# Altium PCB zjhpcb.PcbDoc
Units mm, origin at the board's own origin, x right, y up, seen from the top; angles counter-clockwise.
Board outline 152.4 x 101.6 mm, 4 copper layers (Top, GND, POWER, Bottom), stack 0.776 mm thick; 108 components, 81 nets, 341 pads, 2 vias.
Unrouted connection lines stored in the file: 172.
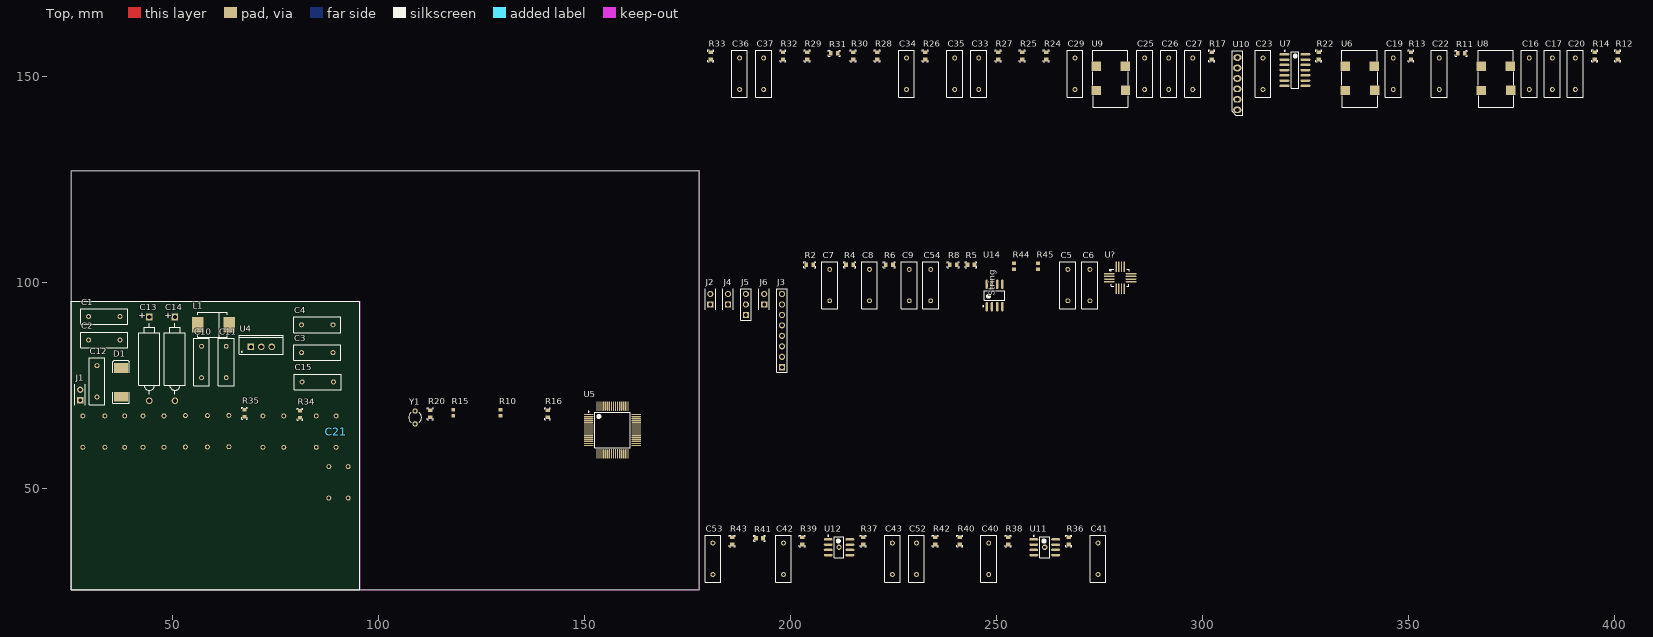
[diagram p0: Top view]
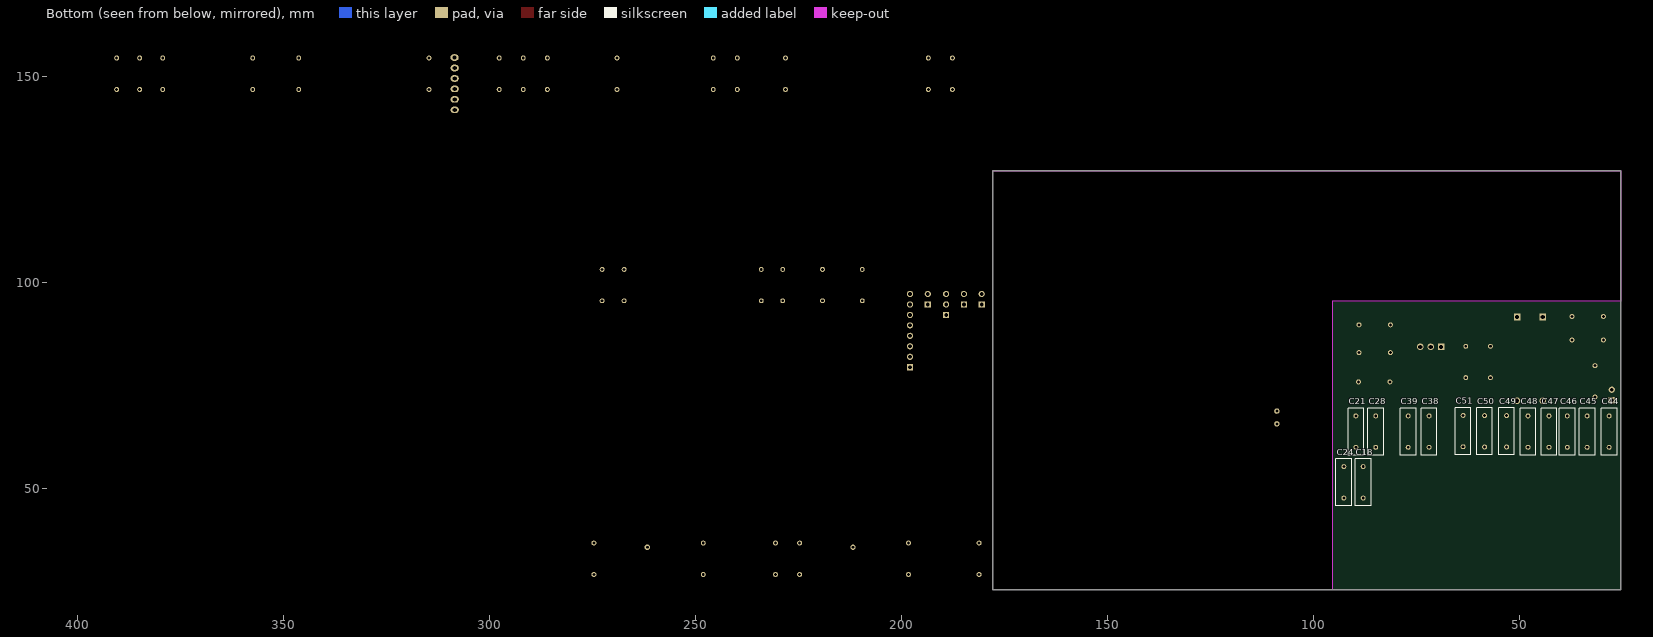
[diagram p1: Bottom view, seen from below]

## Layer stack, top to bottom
Top Solder: solder mask 0.0102, Solder Resist, Dk 3.5
Top: signal copper 0.0356
Dielectric 2: prepreg 0.254, PP-006, Dk 4.1
GND: signal copper 0.035
Dielectric 1: dielectric 0.127, FR-4, Dk 4.8
POWER: signal copper 0.035
Dielectric 3: prepreg 0.254, PP-006, Dk 4.1
Bottom: signal copper 0.0356
Bottom Solder: solder mask 0.0102, Solder Resist, Dk 3.5

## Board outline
25.4,25.4 177.8,25.4 177.8,127 25.4,127
cut-out: 25.4,127 25.4,95.377 95.377,95.377 95.377,25.4 177.8,25.4 177.8,127

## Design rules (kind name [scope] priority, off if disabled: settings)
Clearance [All] p1: gap=0.254 ignorepadtopadclearanceinfootprint=FALSE except(0: Arc-Hole Track-Hole SMDPad-Hole THPad-Hole Via-Hole Fill-Hole Poly-Hole Region-Hole Text-Hole)
PolygonConnect [All] p1: connectstyle=Relief reliefconductorwidth=0.254 reliefentries=4 polygonreliefangle="90 Angle" airgapwidth=0.254
RoomDefinition U_陀螺仪模块 [InComponentClass('U_陀螺仪模块')] p1: confinementstyle=ConfineIn formatcopy=TRUE outline 179.578,140.183 404.368,140.183 404.368,159.106 179.578,159.106
RoomDefinition U_电源模块 [InComponentClass('U_电源模块')] p2: confinementstyle=ConfineIn formatcopy=TRUE outline 25.908,69.85 104.521,69.85 104.521,94.996 25.908,94.996
RoomDefinition U_信号输入模块 [InComponentClass('U_信号输入模块')] p3: confinementstyle=ConfineIn formatcopy=TRUE outline 178.943,77.851 199.771,77.851 199.771,101.219 178.943,101.219
RoomDefinition U_传感器监测模块 [InComponentClass('U_传感器监测模块')] p4: confinementstyle=ConfineIn formatcopy=TRUE outline 202.971,92.583 284.124,92.583 284.124,107.823 202.971,107.823
RoomDefinition U_主控模块 [InComponentClass('U_主控模块')] p5: confinementstyle=ConfineIn formatcopy=TRUE outline 178.943,42.545 313.436,42.545 313.436,60.071 178.943,60.071
RoomDefinition U_CAN总线模块 [InComponentClass('U_CAN总线模块')] p6: confinementstyle=ConfineIn formatcopy=TRUE outline 178.943,26.924 276.86,26.924 276.86,41.402 178.943,41.402
RoutingVias [All] p1: holewidth=0.254 width=0.508 viastyle="Through Hole" minholewidth=0.254 minwidth=0.508 maxholewidth=0.254 maxwidth=0.508
SolderMaskExpansion [All] p1: expansion=0.102
Width [All] p1: maxlimit=0.254 minlimit=0.254 preferedwidth=0.254
Width POWER [All] p2: maxlimit=0.762 minlimit=0.508 preferedwidth=0.508
Width GND [All] p3: maxlimit=0.762 minlimit=0.508 preferedwidth=0.508
30 further rules are at their usual default settings.

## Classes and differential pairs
component class U_电源模块: C1 C2 C3 C4 C10 C11 C12 C13 C14 C15 D1 J1 L1 U1 U4
component class U_陀螺仪模块: C16 C17 C19 C20 C22 C23 C25 C26 C27 C29 C33 C34 C35 C36 C37 R11 R12 R13 R14 R17 R22 R24 R25 R26 R27 R28 R29 R30 R31 R32 R33 U6 U7 U8 U9 U10
component class U_信号输入模块: J2 J3 J4 J5 J6
component class U_传感器监测模块: C5 C6 C7 C8 C9 C54 R2 R4 R5 R6 R8 R44 R45 U2 U14 U?
component class U_主控模块: C18 C21 C24 C28 C38 C39 C44 C45 C46 C47 C48 C49 C50 C51 R10 R15 R16 R20 R34 R35 U5 Y1
component class U_CAN总线模块: C40 C41 C42 C43 C52 C53 R36 R37 R38 R39 R40 R41 R42 R43 U11 U12

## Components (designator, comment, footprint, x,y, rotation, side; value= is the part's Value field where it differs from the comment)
C1 "Cap" RAD-0.3 33.401,91.694 r180 top value=0.1uF
C2 "Cap" RAD-0.3 33.401,85.979 r180 top value=10uF
C3 "Cap" RAD-0.3 85.09,82.931 r180 top value=0.1uF
C4 "Cap" RAD-0.3 85.09,89.662 r180 top value=10uF
C5 "Cap" RAD-0.3 267.233,99.314 r90 top value=0.1uF
C6 "Cap" RAD-0.3 272.567,99.314 r90 top value=0.1uF
C7 "Cap" RAD-0.3 209.448,99.314 r90 top value=0.1uF
C8 "Cap" RAD-0.3 219.1,99.314 r90 top value=0.1uF
C9 "Cap" RAD-0.3 228.752,99.314 r90 top value=0.1uF
C10 "Cap" RAD-0.3 57.023,80.645 r90 top value=0.1uF
C11 "Cap" RAD-0.3 62.992,80.645 r90 top value=0.1uF
C12 "Cap" RAD-0.3 31.623,75.946 r90 top value=1uF
C13 "Cap Pol2" POLAR0.8 44.323,81.407 r90 top value=470uF
C14 "Cap Pol2" POLAR0.8 50.546,81.407 r90 top value=470uF
C15 "Cap" RAD-0.3 85.217,75.819 r180 top value=10uF
C16 "Cap" RAD-0.3 379.222,150.597 r90 top value=22pF
C17 "Cap" RAD-0.3 384.81,150.597 r90 top value=22pF
C18 "Cap" RAD-0.3 87.884,51.435 r90 bottom value=20uF
C19 "Cap" RAD-0.3 346.202,150.597 r90 top value=22uF
C20 "Cap" RAD-0.3 390.398,150.597 r90 top value=22nF
C21 "Cap" RAD-0.3 89.662,63.754 r90 top value=20uF
C22 "Cap" RAD-0.3 357.378,150.597 r90 top value=0.1uF
C23 "Cap" RAD-0.3 314.579,150.597 r90 top value=0.1uF
C24 "Cap" RAD-0.3 92.583,51.435 r90 bottom value=0.1uF
C25 "Cap" RAD-0.3 285.877,150.597 r90 top value=0.1uF
C26 "Cap" RAD-0.3 291.719,150.597 r90 top value=0.01uF
C27 "Cap" RAD-0.3 297.561,150.597 r90 top value=1uF
C28 "Cap" RAD-0.3 84.836,63.754 r90 bottom value=1uF
C29 "Cap" RAD-0.3 268.986,150.597 r90 top value=0.1uF
C33 "Cap" RAD-0.3 245.618,150.597 r90 top value=22uF
C34 "Cap" RAD-0.3 228.092,150.597 r90 top value=0.1uF
C35 "Cap" RAD-0.3 239.776,150.597 r90 top value=22nF
C36 "Cap" RAD-0.3 187.579,150.597 r90 top value=22uF
C37 "Cap" RAD-0.3 193.421,150.597 r90 top value=22nF
C38 "Cap" RAD-0.3 71.882,63.754 r90 bottom value=1uF
C39 "Cap" RAD-0.3 76.962,63.754 r90 bottom value=0.22uF
C40 "Cap" RAD-0.3 248.031,32.893 r90 top value=0.1uF
C41 "Cap" RAD-0.3 274.574,32.893 r90 top value=0.1uF
C42 "Cap" RAD-0.3 198.247,32.893 r90 top value=0.1uF
C43 "Cap" RAD-0.3 224.663,32.893 r90 top value=20pF
C44 "Cap" RAD-0.3 28.194,63.754 r90 bottom value=1uF
C45 "Cap" RAD-0.3 33.528,63.754 r90 bottom value=1uF
C46 "Cap" RAD-0.3 38.354,63.754 r90 bottom value=1uF
C47 "Cap" RAD-0.3 42.799,63.754 r90 bottom value=1uF
C48 "Cap" RAD-0.3 47.879,63.754 r90 bottom value=1uF
C49 "Cap" RAD-0.3 53.086,63.816 r90 bottom value=1uF
C50 "Cap" RAD-0.3 58.42,63.816 r90 bottom value=1uF
C51 "Cap" RAD-0.3 63.627,63.885 r90 bottom value=1uF
C52 "Cap" RAD-0.3 230.505,32.893 r90 top value=0.1uF
C53 "Cap" RAD-0.3 181.102,32.893 r90 top value=20uF
C54 "Cap" RAD-0.3 233.959,99.314 r90 top value=0.1uF
D1 "Diode" SMC 37.465,75.692 r90 top
J1 "POWER" HDR1X2 27.559,71.374 r90 top
J2 "POWER" HDR1X2 180.467,94.615 r90 top
J3 "Header 8" HDR1X8 197.866,79.375 r90 top
J4 "POWER" HDR1X2 184.785,94.615 r90 top
J5 "Header 3" HDR1X3 189.103,92.075 r90 top
J6 "POWER" HDR1X2 193.548,94.615 r90 top
L1 "47uH" DIODE_SMC 59.944,89.662 r180 top
R2 "680R" R0603 204.622,104.267 r0 top
R4 "680R" R0603 214.274,104.267 r0 top
R5 "680R" R0603 243.738,104.267 r0 top
R6 "680R" R0603 223.926,104.267 r0 top
R8 "680R" R0603 239.42,104.267 r0 top
R10 "470R" 1608[0603] 129.54,68.326 r90 top
R11 "10K" R0603 362.712,155.55 r0 top
R12 "10k" R0603 400.685,154.915 r90 top
R13 "47K" R0603 350.52,154.915 r90 top
R14 "47k" R0603 395.097,154.915 r90 top
R15 "1M" 1608[0603] 118.11,68.326 r90 top
R16 "470R" R0603 140.97,68.072 r90 top
R17 "10k" R0603 302.133,154.915 r90 top
R20 "470R" R0603 112.522,68.072 r90 top
R22 "680" R0603 328.168,154.915 r90 top
R24 "10k" R0603 262.001,154.915 r90 top
R25 "100" R0603 256.159,154.915 r90 top
R26 "100k" R0603 232.664,154.915 r90 top
R27 "2.2K" R0603 250.317,154.915 r90 top
R28 "47k" R0603 220.98,154.915 r90 top
R29 "10k" R0603 203.962,154.915 r90 top
R30 "6.8k" R0603 215.138,154.915 r90 top
R31 "100k" R0603 210.566,155.55 r0 top
R32 "220K" R0603 198.12,154.915 r90 top
R33 "100k" R0603 180.594,154.915 r90 top
R34 "220" R0603 80.899,67.945 r90 top
R35 "220" R0603 67.437,68.224 r90 top
R36 "100" R0603 267.462,37.211 r90 top
R37 "100" R0603 217.551,37.211 r90 top
R38 "100" R0603 252.73,37.211 r90 top
R39 "100" R0603 202.819,37.211 r90 top
R40 "120" R0603 241.046,37.211 r90 top
R41 "120" R0603 192.405,37.846 r0 top
R42 "100" R0603 235.077,37.211 r90 top
R43 "100" R0603 185.801,37.211 r90 top
R44 "10K" 1608[0603] 254.152,103.886 r90 top
R45 "10K" 1608[0603] 259.994,103.886 r90 top
U4 "LM7805" TO-220AB 71.501,84.328 r0 top
U5 "Infineon XE162" "Infineon XE162" 156.718,64.135 r0 top
U6 "ENC03" ENC03 338.074,149.454 r90 top
U7 "TLV2374" "TLV 2374" 322.326,151.486 r0 top
U8 "ENC03" ENC03 371.094,149.454 r90 top
U9 "ENC03" ENC03 277.622,149.454 r90 top
U10 "MPX4115" MPX4115 308.356,141.834 r90 top
U11 "CAN收发器" CAN 261.62,35.687 r0 top
U12 "CAN收发器" CAN 211.709,35.687 r0 top
U14 "LM75A(Tempeture)" LM75A 249.453,96.774 r90 top
U? "LIS344ALH" LIS344ALH(Acc) 279.933,101.092 r0 top
Y1 "12MHz" R38 108.839,67.183 r0 top

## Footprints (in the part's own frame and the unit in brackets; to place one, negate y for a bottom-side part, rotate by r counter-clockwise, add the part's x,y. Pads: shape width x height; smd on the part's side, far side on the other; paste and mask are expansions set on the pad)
1608[0603] [mm]
  rect 0.8x0.9 smd: 1(-0.7,0) 2(0.7,0)
CAN [mm]
  oval 2.15x0.6 smd: 1(-2.616,1.905) 2(-2.642,0.635) 3(-2.642,-0.635) 4(-2.616,-1.905) 5(2.642,-1.905) 6(2.642,-0.635) 7(2.642,0.635) 8(2.642,1.905)
  silkscreen extent -2.74,-2.5 1.17,2.89
DIODE_SMC [mil]
  rect 110x150 smd: 1(-150,0) 2(150,0)
  silkscreen extent -130,-120 150,120
ENC03 [mm]
  rect 2.3x2.3 smd: 1(-2.883,-3.607) 2(2.934,-3.505) 3(2.921,3.505) 4(-2.921,3.531)
  silkscreen extent -6.98,-4.19 6.86,4.32
HDR1X2 [mm]
  rect 1.5x1.5 hole 0.9: 1(0,0)
  round 1.5 hole 0.9: 2(2.54,0)
  silkscreen extent -1.27,-1.27 3.81,1.27
HDR1X3 [mm]
  rect 1.5x1.5 hole 0.9: 1(0,0)
  round 1.5 hole 0.9: 2(2.54,0) 3(5.08,0)
  silkscreen extent -1.27,-1.27 6.35,1.27
HDR1X8 [mm]
  rect 1.5x1.5 hole 0.9: 1(0,0)
  round 1.5 hole 0.9: 2(2.54,0) 3(5.08,0) 4(7.62,0) 5(10.16,0) 6(12.7,0) 7(15.24,0) 8(17.78,0)
  silkscreen extent -1.27,-1.27 19.05,1.27
"Infineon XE162" [mm]
  oval 2.3x0.3 smd: 1(-5.8,3.75) 2(-5.8,3.25) 3(-5.8,2.75) 4(-5.8,2.25) 5(-5.8,1.75) 6(-5.8,1.25) 7(-5.8,0.75) 8(-5.8,0.25) 9(-5.8,-0.25) 10(-5.8,-0.75) 11(-5.8,-1.25) 12(-5.8,-1.75) 13(-5.8,-2.25) 14(-5.8,-2.75) 15(-5.8,-3.25) 16(-5.8,-3.75) 33(5.8,-3.75) 34(5.8,-3.25) 35(5.8,-2.75) 36(5.8,-2.25) 37(5.8,-1.75) 38(5.8,-1.25) 39(5.8,-0.75) 40(5.8,-0.25) 41(5.8,0.25) 42(5.8,0.75) 43(5.8,1.25) 44(5.8,1.75) 45(5.8,2.25) 46(5.8,2.75) 47(5.8,3.25) 48(5.8,3.75)
  oval 0.3x2.3 smd: 17(-3.75,-5.8) 18(-3.25,-5.8) 19(-2.75,-5.8) 20(-2.25,-5.8) 21(-1.75,-5.8) 22(-1.25,-5.8) 23(-0.75,-5.8) 24(-0.25,-5.8) 25(0.25,-5.8) 26(0.75,-5.8) 27(1.25,-5.8) 28(1.75,-5.8) 29(2.25,-5.8) 30(2.75,-5.8) 31(3.25,-5.8) 32(3.75,-5.8) 49(3.75,5.8) 50(3.25,5.8) 51(2.75,5.8) 52(2.25,5.8) 53(1.75,5.8) 54(1.25,5.8) 55(0.75,5.8) 56(0.25,5.8) 57(-0.25,5.8) 58(-0.75,5.8) 59(-1.25,5.8) 60(-1.75,5.8) 61(-2.25,5.8) 62(-2.75,5.8) 63(-3.25,5.8) 64(-3.75,5.8)
  silkscreen extent -5.92,-4.3 4.3,4.57
LIS344ALH(Acc) [mm]
  oval 2.6x0.35 smd: 1(-2.642,0.978) 2(-2.642,0.33) 3(-2.642,-0.318) 4(-2.642,-0.965) 9(2.642,-0.965) 10(2.616,-0.318) 11(2.642,0.33) 12(2.642,0.978)
  oval 0.35x2.6 smd: 5(-0.978,-2.642) 6(-0.33,-2.642) 7(0.318,-2.654) 8(0.965,-2.654) 13(0.965,2.654) 14(0.317,2.654) 15(-0.33,2.654) 16(-0.978,2.654)
  silkscreen extent -2.62,-2.1 2.1,2.1
LM75A [mm]
  oval 2.3x0.6 smd: 1(-2.705,1.892) 2(-2.705,0.635) 3(-2.705,-0.635) 4(-2.705,-1.905) 5(2.73,-1.892) 6(2.718,-0.635) 7(2.73,0.635) 8(2.73,1.905)
  silkscreen extent -2.67,-2.5 1.17,2.88
MPX4115 [mm]
  oval 1.6x2 hole 1: 1(0,0) 2(2.54,0) 3(5.08,0) 4(7.62,0) 5(10.16,0) 6(12.7,-0.025)
  round 1 on Top Overlay: 6(-0.927,0.889)
  silkscreen extent -1.28,-1.27 14.35,1.27
POLAR0.8 [mm] "Polarized Capacitor; 2 Leads"
  rect 1.6x1.6 hole 1: 1(10.16,0)
  round 1.6 hole 1: 2(-10.16,0)
  silkscreen extent -8.64,-2.54 8.64,2.54
R38 [mm]
  round 1.3 hole 0.7: 1(0,1.55) 2(0,-1.55)
  silkscreen extent -1.55,-1.19 1.55,1.17
R0603 [mil]
  rect 35x42 smd: 1(-34,0) 2(34,0)
  silkscreen extent -57,-28 57,28
RAD-0.3 [mm] "Radial Cap, Thru-Hole; 2 Leads; 0.3 in Pin Spacing"
  round 1.2 hole 0.7: 1(-3.81,0) 2(3.81,0)
  silkscreen extent -5.71,-1.91 5.71,1.91
SMC [mm]
  rect 2.4x3.3 smd: 1(-3.475,0) 2(3.475,0)
  silkscreen extent -5.07,-2.05 5.43,2.05
"TLV 2374" [mm]
  oval 2.454x0.6 smd: 1(-2.54,3.81) 2(-2.54,2.54) 3(-2.54,1.27) 4(-2.54,0) 5(-2.54,-1.27) 6(-2.54,-2.54) 7(-2.54,-3.81) 8(2.54,-3.81) 9(2.54,-2.54) 10(2.54,-1.27) 11(2.54,0) 12(2.54,1.27) 13(2.54,2.54) 14(2.54,3.81)
  silkscreen extent -2.52,-4.4 0.9,4.78
TO-220AB [mm]
  rect 1.6x1.6 hole 1: 1(-2.54,0)
  round 1.6 hole 1: 2(0,0) 3(2.54,0)
  silkscreen extent -5.35,-1.85 5.35,2.85

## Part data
C1 C2 C3 C4 C5 C6 C7 C8 C9 C10 C11 C12 C15 C16 C17 C18 C19 C20 C21 C22 C23 C24 C25 C26 C27 C28 C29 C33 C34 C35 C36 C37 C38 C39 C40 C41 C42 C43 C44 C45 C46 C47 C48 C49 C50 C51 C52 C53 C54: "Capacitor"
C13 C14: "Polarized Capacitor (Axial)"
D1: "Default Diode"
J1 J2 J4 J6: library part "Header 2", "Header, 2-Pin"
J3: "Header, 8-Pin"
J5: "Header, 3-Pin"
L1: library part Inductor47uH
R2 R4 R5 R6 R8 R11 R12 R13 R14 R16 R17 R20 R22 R24 R25 R26 R27 R28 R29 R30 R31 R32 R33 R34 R35 R36 R37 R38 R39 R40 R41 R42 R43: library part R0603
R10 R15 R44 R45: library part R0805
U4: library part 7805
U11 U12: library part CAN
U?: library part ACC(LIS344ALH)
Y1: library part XTAL, "Crystal Oscillator"

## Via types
v1: diameter 1.27, hole 0.711, Top to Bottom, 2 vias

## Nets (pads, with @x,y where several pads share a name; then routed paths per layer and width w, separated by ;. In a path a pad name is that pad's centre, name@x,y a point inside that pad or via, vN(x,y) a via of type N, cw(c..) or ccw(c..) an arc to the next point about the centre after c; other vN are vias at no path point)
1IN+: U6.4 U7.3
3V3: C3.2 C4.2 C6.2 U?.14 U?.15
5VA: C1.2 C2.2 C22.2 C23.2 C25.2 C26.2 C27.2 C29.2 L1.2 R22.1 U6.3 U7.4 U8.2 U9.3 U10.3
5VC: C5.2 C54.2 U14.5 U14.6 U14.7 U14.8
5VD: C15.2 C40.2 C42.2 J3.7 J5.2 L1.1 R44.2 R45.2 U4.3 U5.40 U11.3 U12.3
ACC-X: C7.1 R2.2 U5.19
ACC-Y: C8.1 C24.2 R4.2 R16.1 R20.2 U5.20
ACC-Z: C9.1 R6.2 U5.21
CANR-1: U5.25 U12.1
CANR-2: U5.29 U11.1
CANRX-1: J4.1 R41.2 R43.1
CANRX-2: J6.1 R40.2 R42.1
CANT-1: U5.26 U12.4
CANT-2: U5.27 U11.4
CANTX-1: J4.2 R39.1 R41.1
CANTX-2: J6.2 R38.1 R40.1
CLK: J3.2 U5.36
CS: J3.1 U5.35
GND: C1.1 C2.1 C3.1 C4.1 C10.1 C11.1 C12.1 C13.2 C14.2 C15.1 J1.1 U4.2
GX: C16.2 C19.2 R13.1 U5.10 U7.1
GY: C33.1 C36.2 R28.2 U5.11 U7.7
GZ: C17.2 C20.2 R14.1 U5.14 U7.8
High: C37.2 R31.1 U5.15
IN: J3.4 U5.42
LED1: U5.51
LED2: U5.43
MISO: J3.3 U5.37
MOSI: J3.5 U5.58
NetC10_2: C10.2 C11.2 C13.1 C14.1 D1.2 U4.1
NetC18_1: C18.1 R10.2 Y1.2
NetC19_1: C19.1 R11.1 R13.2 R17.1 U7.2
NetC20_1: C20.1 U7.9 U8.1
NetC21_1: C21.1 R15.1 U5.60 Y1.1
NetC33_2: C33.2 R24.1 R28.1 R29.1 U7.6
NetC34_1: C34.1 R26.1 R31.2 U7.14
NetC34_2: C34.2 R25.2 R30.2 R33.2
NetC35_2: C35.2 R25.1 R27.2 R32.2
NetC41_1: C41.1 R38.2 U11.7
NetC43_1: C43.1 R39.2 U12.7
NetC44_2: C44.2 C45.2 C46.2 C47.2 C48.2 C49.2 C50.2 C51.2 U5.2 U5.16 U5.18 U5.32 U5.34 U5.48 U5.50 U5.64
NetC52_2: C52.2 R42.2 U11.6
NetC53_2: C53.2 R43.2 U12.6
NetR2_1: R2.1 U?.12
NetR4_1: R4.1 U?.10
NetR5_1: R5.1
NetR6_1: R6.1 U?.8
NetR8_1: R8.1
NetR10_1: R10.1 R15.2 U5.61
NetR12_1: R12.1 R14.2
NetR17_2: R17.2 U6.1
NetR22_2: R22.2 R26.2 U7.13
NetR24_2: R24.2 U9.1
NetR34_2: R34.2 U5.38
NetR35_2: R35.2 U5.39
NetR36_1: R36.1 U11.8
NetR37_1: R37.1 U12.8
NetU7_5: U7.5 U9.4
NetU7_10: U7.10 U8.4
NetU7_12: U7.12 U10.1
NetU10_4: U10.4
NetU11_5: U11.5
OS-H: R33.1
OS-X: R11.2
OS-Y: R29.2
OS-Z: R12.2
OUT: J3.6 U5.28
P10.4: U5.44
P-OFF1: R27.1 U5.54
P-OFF2: R32.1 U5.53
PPM: J5.1 U5.31
RXD-1: J2.1
RXD-2: U5.56
SCL-1: R8.2 R45.1 U5.45 U14.2
SCL-2: U5.30
SDA-1: R5.2 R44.1 U5.47 U14.1
SEV3: U5.5
TXD-1: J2.2
TXD-2: U5.59
VCC: C28.2 C39.1 R16.2 U5.9 U5.12
VDDI1: U5.24 U5.41 U5.57
VDIM: C38.1 U5.6
pads on no net: C5.1 C6.1 C7.2 C8.2 C9.2 C12.2 C16.1 C17.1 C18.2 C21.2 C22.1 C23.1 C24.1 C25.1 C26.1 C27.1 C28.1 C29.1 C35.1 C36.1 C37.1 C38.2 C39.2 C40.1 C41.2 C42.1 C43.2 C44.1 C45.1 C46.1 C47.1 C48.1 C49.1 C50.1 C51.1 C52.1 C53.1 C54.1 D1.1 J1.2 J3.8 J5.3 R20.1 R30.1 R34.1 R35.1 R36.2 R37.2 U5.1 U5.3 U5.4 U5.7 U5.8 U5.13 U5.17 U5.22 U5.23 U5.33 U5.46 U5.49 U5.52 U5.55 U5.62 U5.63 U6.2 U7.11 U8.3 U9.2 U10.2 U10.5 U10.6 U11.2 U12.2 U12.5 U14.3 U14.4 U?.1 U?.2 U?.3 U?.4 U?.5 U?.6 U?.7 U?.9 U?.11 U?.13 U?.16
copper on no net:
  other v1: 211.709,35.687 261.62,35.687

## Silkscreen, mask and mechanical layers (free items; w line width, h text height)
Top Overlay:
  lines w0.254: 25.4,25.4 95.4,25.4 95.4,95.4 ; 25.423,25.423 25.423,95.4 95.423,95.4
